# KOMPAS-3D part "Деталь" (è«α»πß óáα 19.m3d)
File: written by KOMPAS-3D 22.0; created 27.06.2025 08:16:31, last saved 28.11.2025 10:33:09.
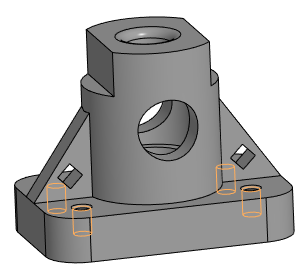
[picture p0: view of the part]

Document properties: Автор: alymovy@yandex.ru; Организация: HP; Полное имя файла: Корпус вар 19.cdw

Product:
- Part/product: Деталь
    Материал: Фторопласт-4 ГОСТ 10007-80 Е (density 2200 kg/m3)
    Масса: 1.167941
    Форматы листов документа: A3

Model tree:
1. Эскиз:1
2. Элемент выдавливания:1
     Расстояние 1 = 25
3. Эскиз:2  (with: Элемент выдавливания:1)
4. Элемент выдавливания:2
     Расстояние 1 = 85
5. Эскиз:3  (with: Элемент выдавливания:1, Элемент выдавливания:2)
6. Ребро жесткости:1
     Толщина стенки 1 = 15; Толщина стенки 2 = 1
7. Зеркальный массив:1
8. Экземпляр ( 1 )
9. Экземпляр ( 2 )  (with: Ребро жесткости:1)
10. Эскиз:4  (with: Элемент выдавливания:1, Элемент выдавливания:2)
11. Элемент вращения:1
     Угол 1 = 360
12. Скругление:1  (with: Элемент вращения:1)
     Радиус = 5
13. Эскиз:5  (with: Элемент выдавливания:2)
14. Элемент выдавливания:3
     Расстояние 1 = 47.5
15. Эскиз:6  (with: Ребро жесткости:1)
16. Элемент выдавливания:4
     Расстояние 1 = 40
17. Скругление:2  (with: Элемент выдавливания:1)
     Радиус = 20
18. Эскиз:7  (with: Элемент выдавливания:1, Элемент выдавливания:2)
19. Отверстие:1  (with: Элемент выдавливания:1)  (labels: M10)
     Глубина выреза = 20; Диаметр отверстия = 8.3762; Угол конуса дна = 118; Расстояние 1 = 22.5; Расстояние 2 = 118; Диаметр зенковки = 11.5762; Глубина зенковки = 1.6; Угол зенковки = 90
20. M10  (with: Отверстие:1)  (labels: cil0_24705-2004 coarse)
     Длина резьбы = 15; Шаг резьбы = 1.5; Номинальный диаметр резьбы = 10
21. Зеркальный массив:2  (with: Экземпляр ( 1 ), Экземпляр ( 2 ), Отверстие:1)
22. Зеркальный массив:3  (with: Экземпляр ( 1 ), Экземпляр ( 2 ), Зеркальный массив:2, Отверстие:1)
23. Экземпляр ( 2 )  (with: Отверстие:1)

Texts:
  Точка начала. Х
  Точка начала. Y
  Точка начала. Z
